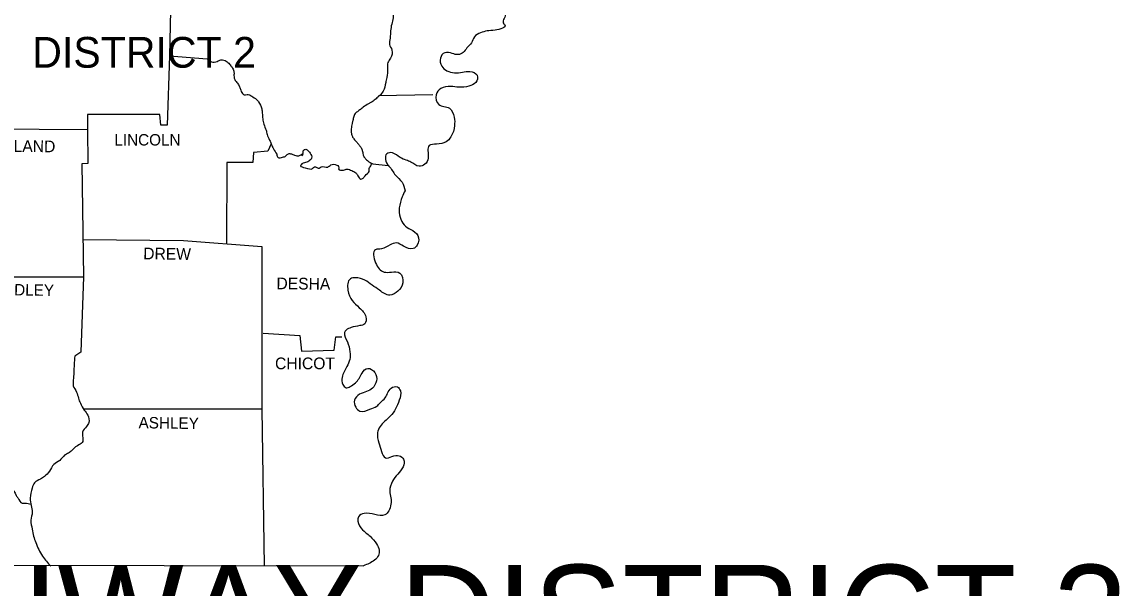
# Model space of a CAD drawing. Extents: x 3046 to 131673, y -8885 to 10756.
# Drawn here: x 66781 to 70739, y 4994 to 7032 of the extents above; entities that cross this region are included whole.
import ezdxf

# ---------------------------------------------------------------- set-up
doc = ezdxf.new("R2010")
doc.units = 0
for name, color, linetype in [('1', 7, 'Continuous'), ('2', 7, 'Continuous'), ('3', 7, 'Continuous')]:
    doc.layers.add(name, color=color, linetype=linetype)

msp = doc.modelspace()

# ---------------------------------------------------------------- linework, layer by layer
at = {"layer": '1'}
msp.add_line((68063.3, 6768.2), (68259, 6771.2), dxfattribs=at)
for points in [[(67319.8, 7294.1), (67311.9, 6910.1), (67447.9, 6899.3)], [(67311.9, 6910.1), (67303.1, 6661.6), (67280.6, 6661.6), (67276.6, 6699.7), (67016.4, 6699.7), (67016.4, 6644.9)], [(66668.1, 6647.9), (67016.4, 6645.9)], [(67016.4, 6645.9), (67017.4, 6523.6), (66996.8, 6522.6), (67002.7, 6116.6)], [(67677.8, 6594.1), (67666.1, 6567.6), (67614.2, 6562.8), (67611.3, 6527.5), (67518.3, 6527.5), (67517.3, 6235)], [(67787.4, 6551), (67790.3, 6553.9), (67793.2, 6556.9), (67793.2, 6556.9)], [(66999.8, 6249.7), (67362.7, 6246.7), (67644.5, 6225.2)], [(67644.5, 6225.2), (67644.5, 5640.1), (67652.4, 5077.5)], [(66560.5, 6115.6), (67002.7, 6116.6)], [(67002.7, 6116.6), (66992.9, 5844.6), (66971.4, 5830.9)], [(67649.4, 5913.1), (67780.5, 5905.3), (67786.4, 5848.5), (67904.8, 5852.4), (67909.7, 5900.4), (67932.2, 5900.4)], [(64421.7, 5874.9), (64423.6, 5083.4), (68009.5, 5077.5)], [(67002.3, 5641.1), (67644.5, 5641.1)]]:
    msp.add_lwpolyline(points, dxfattribs=at)
for points in [[(68833.3, 7720.2), (68810.8, 7691.8), (68777.5, 7709.4), (68777.5, 7732.9), (68782.4, 7757.4), (68770.7, 7773), (68750.1, 7766.2), (68750.1, 7735.9), (68748.2, 7706.5), (68742.3, 7664.4), (68756, 7651.7), (68787.3, 7647.8), (68809.8, 7641.9), (68823.5, 7619.4), (68822.5, 7592), (68811.8, 7565.6), (68796.1, 7544.1), (68771.7, 7536.3), (68752.1, 7549), (68744.3, 7574.4), (68735.5, 7596.9), (68718.8, 7613.6), (68701.2, 7595), (68697.3, 7560.7), (68698.3, 7531.4), (68698.3, 7491.3), (68723.7, 7464.8), (68739.4, 7434.5), (68734.5, 7407.1), (68715.9, 7374.8), (68708.1, 7346.5), (68700.2, 7308.3), (68701.2, 7266.2), (68694.4, 7225.1), (68680.7, 7197.7), (68655.2, 7175.2), (68638.6, 7160.6), (68624.9, 7145.9), (68618, 7116.5), (68613.2, 7096), (68594.6, 7071.5), (68579.9, 7069.6), (68568.1, 7079.4), (68564.2, 7096), (68564.2, 7112.6), (68556.4, 7129.3), (68531.9, 7136.1), (68512.4, 7135.1), (68503.6, 7121.4), (68516.3, 7083.3), (68521.2, 7058.8), (68514.3, 7025.5), (68518.2, 7021.6), (68483, 7003), (68454.7, 7000.1), (68431.2, 6993.3), (68408.7, 6978.6), (68397.9, 6957.1), (68382.2, 6939.4), (68368.6, 6922.8), (68350, 6915), (68329.4, 6918.9), (68302, 6921.8), (68286.4, 6902.3), (68291.3, 6873.9), (68309.8, 6857.3), (68337.2, 6849.4), (68365.6, 6851.4), (68393, 6854.3), (68418.4, 6840.6), (68413.6, 6814.2), (68389.1, 6801.5), (68352.9, 6797.6), (68323.5, 6800.5), (68288.3, 6792.7), (68270.7, 6770.2), (68280.5, 6735.9), (68318.7, 6722.2), (68336.3, 6689.9), (68337.2, 6659.6), (68324.5, 6619.5), (68306.9, 6600.9), (68272.7, 6593.1), (68246.2, 6588.2), (68242.3, 6543.2), (68230.6, 6520.7), (68210, 6513.8), (68180.7, 6528.5), (68163.1, 6535.4), (68141.6, 6545.1), (68114.2, 6561.8), (68093.6, 6558.8), (68099.5, 6515.8), (68101.4, 6513.8), (68124.9, 6481.5), (68148.4, 6456.1), (68159.2, 6425.8)], [(67819.7, 7405.2), (67822.6, 7365), (67846.1, 7359.2), (67855.9, 7348.4), (67860.8, 7325.9), (67877.4, 7316.1), (67899.9, 7302.4), (67913.6, 7292.6), (67923.4, 7277), (67929.2, 7251.6), (67944.9, 7234.9), (67966.4, 7227.1), (67982.1, 7208.5), (67991.9, 7182.1), (68007.5, 7170.3), (68023.2, 7149.8), (68031, 7141), (68044.7, 7117.5), (68058.4, 7105.8), (68068.2, 7098.9), (68083.8, 7094), (68103.4, 7081.3), (68116.1, 7061.7), (68116.1, 7047.1), (68111.2, 7024.6), (68107.3, 7001.1), (68105.4, 6974.7), (68103.4, 6951.2), (68112.2, 6931.6), (68107.3, 6902.3), (68097.5, 6886.6), (68096.6, 6865.1), (68093.6, 6832.8), (68089.7, 6814.2), (68080.9, 6783.9), (68068.2, 6768.2)], [(67447.9, 6899.3), (67462.5, 6889.5), (67483.1, 6890.5), (67496.8, 6896.4), (67507.6, 6895.4), (67522.2, 6886.6), (67532, 6874.9), (67538.9, 6866.1), (67543.8, 6852.4), (67543.8, 6839.6), (67548.6, 6822), (67554.5, 6815.2), (67562.3, 6802.5), (67567.2, 6790.7), (67570.2, 6782.9), (67580.9, 6770.2), (67590.7, 6771.2), (67599.5, 6770.2), (67611.3, 6763.3), (67628.9, 6749.6), (67631.8, 6745.7), (67643.6, 6720.3), (67645.5, 6704.6), (67647.5, 6684.1), (67651.4, 6664.5), (67659.2, 6643), (67663.1, 6628.3), (67671.9, 6607.8), (67677.8, 6594.1), (67685.6, 6576.5), (67697.4, 6556.9), (67702.3, 6545.1), (67718.9, 6546.1), (67730.6, 6551), (67739.4, 6558.8), (67750.2, 6557.9), (67761.9, 6553.9), (67777.6, 6551), (67787.4, 6556.9), (67792.3, 6560.8), (67793.2, 6569.6), (67802.1, 6574.5), (67811.8, 6567.6), (67822.6, 6552), (67822.6, 6542.2), (67818.7, 6536.3), (67806, 6528.5), (67788.4, 6522.6), (67783.5, 6515.8), (67800.1, 6508), (67826.5, 6506), (67833.4, 6511.9), (67851, 6507), (67857.8, 6511.9), (67881.3, 6510.9), (67892.1, 6518.7), (67913.6, 6517.7), (67920.4, 6512.9), (67920.4, 6504.1), (67938.1, 6500.1), (67950.8, 6503.1), (67967.4, 6498.2), (67982.1, 6490.4), (67989.9, 6479.6), (67999.7, 6467.8), (68008.5, 6470.8), (68015.3, 6479.6), (68030, 6495.2), (68030, 6505), (68033.9, 6511.9), (68040.3, 6524.7)], [(68068.2, 6768.2), (68061.6, 6762.1), (68054.9, 6756.3), (68048, 6750.8), (68040.8, 6745.7), (68036.4, 6743.2), (68031.9, 6740.9), (68027.4, 6738.6), (68023.2, 6735.9), (68004.6, 6722.2), (67993.3, 6713.9), (67987.7, 6709.8), (67982.1, 6705.6), (67977.3, 6700), (67974.6, 6692.9), (67972.9, 6685), (67972.2, 6681.1), (67971.3, 6677.2), (67970.1, 6672.4), (67968.9, 6667.5), (67967, 6657.6), (67965.7, 6647.8), (67965.5, 6643), (67965.4, 6638.1), (67966.1, 6632), (67967.6, 6626), (67970, 6620.2), (67971.5, 6617.4), (67973.3, 6614.6), (67977.6, 6609.1), (67982.1, 6604.1), (67986.6, 6599.2), (67990.9, 6594.1), (67997, 6585.9), (68002.6, 6577.4), (68004.3, 6574.1), (68005.5, 6570.5), (68007, 6562.9), (68008.5, 6555.2), (68009.7, 6551.5), (68010.5, 6549.8), (68011.4, 6548.1), (68013.6, 6544.9), (68020.9, 6536.5), (68026.6, 6531.7), (68031.3, 6528.5), (68033, 6527.5), (68038.1, 6524.9), (68043.3, 6522.8)], [(68159.2, 6425.8), (68149.4, 6403.3), (68138.6, 6364.1), (68141.6, 6330.9), (68156.2, 6302.5), (68179.7, 6286.8), (68205.2, 6264.3), (68203.2, 6230.1), (68188.5, 6217.4), (68154.3, 6226.2), (68127.9, 6237.9), (68105.4, 6231.1), (68075, 6216.4), (68052.5, 6213.5), (68053.5, 6166.5), (68083.8, 6133.2), (68110.3, 6133.2), (68140.6, 6129.3), (68151.3, 6094.1), (68133.7, 6064.7), (68104.4, 6050.1), (68067.2, 6067.7), (68040.8, 6086.3), (68014.4, 6103.9), (67981.1, 6112.7), (67962.5, 6108.8), (67953.7, 6067.7), (67969.4, 6030.5), (67994.8, 6005.1), (68018.3, 5971.8), (68014.4, 5947.3), (67996.8, 5940.5), (67965.4, 5933.6), (67946.9, 5923.9), (67942, 5916), (67951.7, 5882.8), (67960.6, 5846.6), (67960.6, 5819.2), (67949.8, 5793.7), (67933.2, 5754.6), (67935.1, 5729.2), (67946.9, 5717.4), (67961.5, 5721.3), (67981.1, 5735), (67993.8, 5750.7), (68004.6, 5770.2), (68025.1, 5786.9), (68050.6, 5772.2), (68056.4, 5741.9), (68041.8, 5715.5), (68021.2, 5703.7), (67995.8, 5693.9), (67977.2, 5672.4), (67982.1, 5647), (67996.8, 5633.3), (68033, 5640.1), (68057.4, 5650.9), (68071.1, 5664.6), (68087.7, 5681.2), (68096.6, 5697.8), (68109.3, 5715.5), (68131.8, 5720.3), (68142.5, 5705.7), (68138.6, 5672.4), (68124.9, 5641.1), (68106.3, 5614.7), (68085.8, 5596.1), (68060.4, 5556), (68065.2, 5518.8), (68075, 5488.5), (68088.7, 5465), (68112.2, 5469.9), (68138.6, 5472.8), (68154.3, 5460.1), (68152.3, 5432.7), (68132.8, 5406.3), (68114.2, 5380.8), (68104.4, 5345.6), (68108.3, 5321.2), (68108.3, 5298.7), (68100.5, 5274.2), (68086.8, 5260.5), (68050.6, 5261.5), (68012.4, 5265.4), (67991.9, 5253.6), (67995.8, 5220.4), (68018.3, 5195.9), (68033.9, 5183.2), (68056.4, 5155.8), (68066.2, 5133.3), (68063.3, 5113.7), (68049.6, 5097.1), (68009.5, 5077.5)], [(66971.4, 5830.9), (66968.5, 5800.6), (66967.5, 5772.2), (66965.5, 5744.8), (66965.5, 5724.3), (66977.3, 5701.8), (66984.1, 5680.2), (66991, 5661.6), (67004.7, 5637.2), (67017.4, 5618.6), (67021.3, 5592.2), (67013.5, 5578.5), (66998.8, 5557.9), (66997.8, 5520.8), (66980.2, 5509), (66957.7, 5489.4), (66945, 5480.6), (66931.3, 5471.8), (66916.6, 5456.2), (66895.1, 5441.5), (66879.4, 5417), (66861.8, 5398.5), (66847.1, 5388.7), (66826.6, 5375.9), (66817.8, 5356.4), (66810.9, 5320.2), (66813.9, 5293.8), (66817.8, 5270.3), (66812.9, 5240.9), (66817.8, 5208.6), (66822.7, 5183.2), (66830.5, 5160.7), (66841.3, 5135.3), (66855, 5111.8), (66884.3, 5075.6)], [(65995.9, 5604.9), (66011.6, 5615.7), (66026.2, 5621.5), (66040.9, 5618.6), (66056.6, 5616.6), (66070.3, 5618.6), (66087.9, 5615.7), (66102.6, 5606.9), (66119.2, 5600), (66135.8, 5600), (66150.5, 5600), (66163.2, 5591.2), (66186.7, 5592.2), (66206.3, 5600), (66225.8, 5605.9), (66252.3, 5608.8), (66275.7, 5592.2), (66292.4, 5578.5), (66306.1, 5562.8), (66315.9, 5545.2), (66326.6, 5535.4), (66344.2, 5528.6), (66357.9, 5525.6), (66374.6, 5520.8), (66383.4, 5516.8), (66391.2, 5498.2), (66403.9, 5472.8), (66428.4, 5464), (66458.7, 5475.7), (66483.2, 5482.6), (66500.8, 5488.5), (66511.5, 5492.4), (66521.3, 5493.4), (66518.4, 5495.3), (66530.1, 5498.2), (66540.9, 5490.4), (66547.7, 5479.7), (66559.5, 5464), (66570.2, 5450.3), (66581, 5445.4), (66591.8, 5451.3), (66606.4, 5446.4), (66619.2, 5441.5), (66633.8, 5437.6), (66646.6, 5436.6), (66663.2, 5432.7), (66675.9, 5425.8), (66687.6, 5419), (66699.4, 5406.3), (66711.1, 5386.7), (66715, 5371.1), (66728.7, 5355.4), (66741.5, 5355.4), (66760, 5330), (66766.9, 5320.2), (66781.6, 5302.6), (66792.3, 5302.6), (66812.9, 5298.7)]]:
    msp.add_spline(points, degree=3, dxfattribs=at)
at = {"layer": '3'}
msp.add_line((68043.3, 6522.8), (68098.5, 6515.8), dxfattribs=at)

# ---------------------------------------------------------------- texts
at = {"layer": '2'}
for s, height, rotation, p in [('CLEVELAND', 42.07, 359.3377, (66566.3, 6567.6)), ('DREW', 42.06, 359.2258, (67217, 6179.2)), ('DESHA', 42.06, 359.3704, (67696.4, 6071.6)), ('BRADLEY', 41.08, 359.1449, (66639.7, 6051)), ('ASHLEY', 41.09, 359.2361, (67200.3, 5571.6))]:
    msp.add_text(s, height=height, rotation=rotation, dxfattribs=at).set_placement(p)
for s, height, p in [('LINCOLN', 41.09, (67113.3, 6588.2)), ('CHICOT', 42.07, (67691.5, 5783.9)), ('ARKANSAS HIGHWAY DISTRICT 3', 360, (62949.6, 4720.5))]:
    msp.add_text(s, height=height, dxfattribs=at).set_placement(p)
at = {"layer": '3'}
msp.add_text('DISTRICT 2', height=110.56, dxfattribs=at).set_placement((66817.8, 6868))

doc.saveas('drawing.dxf')
